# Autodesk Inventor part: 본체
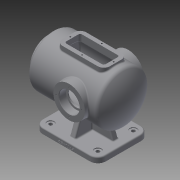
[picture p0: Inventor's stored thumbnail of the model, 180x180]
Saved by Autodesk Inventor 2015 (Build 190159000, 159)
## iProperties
Created: 2021-11
Part Number: 본체
Material: 일반
Document SubType Name: Modeling
Designer: 101698
Mass: 1311.33 g
Surface Area: 2404.16 cm^2
Volume: 1311.33 cm^3
Density: 1 g/cm^3
Appearance: 기본값
Author: 101698
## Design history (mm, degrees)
sketch "스케치1"
  geometry: L1 (-80, -65)-(80, -65); L2 (80, -65)-(80, 65); L3 (80, 65)-(-80, 65); L4 (-80, 65)-(-80, -65); L5 (-80, -65)-(80, 65); L6 (80, -65)-(-80, 65); 1 further point
  constraints: 12 end point, 2 midpoint, 2 parallel, 1 horizontal, 1 perpendicular
  dimensions: "d0" = 160 distance of L1.start L1.end; "d1" = 130 distance of L1.end L2.end
extrude "돌출1" new body sketch "스케치1" distance "d2" = 14; taper "d3" = 0 deg
sketch "스케치2"
  geometry: L1 (-7, -50)-(7, -50); L2 (7, -50)-(7, 50); L3 (7, 50)-(-7, 50); L4 (-7, 50)-(-7, -50); L5 (-7, -50)-(7, 50); L6 (7, -50)-(-7, 50); 1 further point
  constraints: 12 end point, 2 midpoint, 2 parallel, 1 horizontal, 1 perpendicular
  dimensions: "d4" = 14 distance of L2.end L3.end; "d5" = 100 distance of L1.end L2.end
extrude "돌출2" join sketch "스케치2" distance "d6" = 100; taper "d7" = 0 deg
sketch "스케치3"
  geometry: L1 (-7, -50)-(-7, 50) reference; L2 (-7, 50)-(7, 50) reference; L3 (7, 50)-(7, -50) reference; L4 (7, -50)-(-7, -50) reference; L5 (-80, -65)-(-80, 65) reference; L6 (-80, 65)-(80, 65) reference; L7 (80, 65)-(80, -65) reference; L8 (80, -65)-(-80, -65) reference; L9 (-60, -7)-(60, -7); L10 (60, -7)-(60, 7); L11 (60, 7)-(-60, 7); L12 (-60, 7)-(-60, -7); L13 (-60, -7)-(60, 7); L14 (60, -7)-(-60, 7); 1 further point
  constraints: 12 end point, 2 midpoint, 2 parallel, 1 horizontal, 1 perpendicular
  dimensions: "d8" = 14 distance of L11.end L9.start; "d9" = 120 distance of L10.end L11.end
extrude "돌출3" join sketch "스케치3" distance "d10" = 100; taper "d11" = 0 deg
feature "면 기울기1" dims angle "d12" = 20 deg
feature "면 기울기2" dims angle "d13" = 20 deg
feature "면 기울기3" dims angle "d14" = 20 deg
feature "면 기울기4" dims angle "d15" = 20 deg
sketch "스케치8"
  geometry: L1 (-80, 0)-(-80, 14) reference; L2 (-80, 14)-(-60, 14) reference; L3 (-60, 14)-(-23.603, 114) reference; L4 (-23.603, 114)-(23.603, 114) reference; L5 (23.603, 114)-(60, 14) reference; L6 (60, 14)-(80, 14) reference; L7 (80, 14)-(80, 0) reference; L8 (80, 0)-(-80, 0) reference; L9 (-75.993, 179)-(100, 179); L10 (106.737, 51.75)-(-106.612, 176.178); L11 (-109.588, 46.16)-(109.588, 181.84); L12 (-100, 114)-(100, 114); L13 (100, 179)-(100, 114); L14 (80, 0)-(-80, 0) reference; A1 r 95.786 centre (0, 114) between (80, 61.322) and (82.742, 65.743); A2 r 100 centre (0, 114) between (-75.993, 179) and (-100, 114); 3 further points
  constraints: 10 end point, 4 point on circle, 3 midpoint, 3 point on line, 2 centre point, 2 parallel, 1 coincident, 1 horizontal, 1 perpendicular
  dimensions: "d33" = 10 distance of L9.end L11.end; "d34" = 200 distance of L12.start L12.end; "d35" = 65 distance of L9.end L12.end; "d36" = 100 radius of A2; "d142" = 114 vertical distance of L7.end L12.end; "d143" = 20 distance from line of L7 L12.end
revolve "회전1" sketch "스케치8" stored, may be unused: angle "d37" = 90 deg
sketch "스케치10"
  geometry: C1 r 65 at (0, 0) reference; C2 r 47.5 at (0, 0); 1 further point
  constraints: 1 centre point, 1 coincident
  dimensions: "d41" = 95 diameter of C2
extrude "돌출7" join sketch "스케치10" distance "d42" = 10; taper "d43" = 0 deg
sketch "스케치11"
  geometry: C1 r 47.5 at (0, 0) reference; 1 further point
hole "구멍1" sketch "스케치11" at (0, 0) diameter "d44" = 65; stored, may be unused: countersink angle "d48" = 90 deg, drill point angle "d50" = 118 deg; dims "d45" = 6, "d46" = 4, "d47" = 2, "d49" = 40
sketch "스케치12"
  geometry: C1 r 32.5 at (0, 0) reference; 2 further points
  constraints: 1 horizontal alignment
  dimensions: "d51" = 40 distance of C1.centre point (40, 0)
hole "구멍2" sketch "스케치12" at (40, 0) diameter "d52" = 3.242; stored, may be unused: countersink angle "d56" = 90 deg, drill point angle "d58" = 118 deg; dims "d53" = 11, "d54" = 4, "d55" = 2, "d57" = 13
node "작업 평면1"
sketch "스케치13"
  geometry: C1 r 40 at (-17, 114); 1 further point
  constraints: 1 centre point
  dimensions: "d63" = 80 diameter of C1; "d64" = 17 horizontal distance of point (0, 0) C1.centre; "d65" = 114 vertical distance of point (0, 0) C1.centre
extrude "돌출8" join sketch "스케치13" distance "d66" = 150; taper "d67" = 0 deg
node "작업 평면2"
sketch "스케치15"
  geometry: L1 (-60, -30)-(60, -30); L2 (60, -30)-(60, 30); L3 (60, 30)-(-60, 30); L4 (-60, 30)-(-60, -30); L5 (-60, -30)-(60, 30); L6 (60, -30)-(-60, 30); 1 further point
  constraints: 12 end point, 2 midpoint, 2 parallel, 1 horizontal, 1 perpendicular
  dimensions: "d69" = 120 distance of L2.end L3.end; "d70" = 60 distance of L3.end L1.start
extrude "돌출9" join sketch "스케치15" stored distance "d71" = 150; taper "d72" = 0 deg
sketch "스케치16"
  geometry: L1 (-50, -20)-(50, -20); L2 (50, -20)-(50, 20); L3 (50, 20)-(-50, 20); L4 (-50, 20)-(-50, -20); L5 (-50, -20)-(50, 20); L6 (50, -20)-(-50, 20); 1 further point
  constraints: 12 end point, 2 midpoint, 2 parallel, 1 horizontal, 1 perpendicular
  dimensions: "d73" = 100 distance of L2.end L3.end; "d74" = 40 distance of L1.end L2.end
extrude "돌출10" cut sketch "스케치16" distance "d75" = 30; taper "d76" = 0 deg
sketch "스케치17"
  geometry: C1 r 40 at (0, 0) reference; 1 further point
hole "구멍3" sketch "스케치17" at (0, 0) diameter "d77" = 42; stored, may be unused: countersink angle "d81" = 90 deg, drill point angle "d83" = 118 deg; dims "d78" = 11, "d79" = 52, "d80" = 18, "d82" = 13
sketch "스케치18"
  geometry: C1 r 21 at (0, 0) reference; C2 r 40 at (0, 0) reference; C3 r 26 at (0, 0); 1 further point
  constraints: 1 centre point, 1 coincident
  dimensions: "d84" = 52 diameter of C3
extrude "돌출11" cut sketch "스케치18" distance "d85" = 18; taper "d86" = 0 deg
sketch "스케치19"
  geometry: C1 r 26 at (0, 0) reference; 2 further points
  constraints: 1 horizontal alignment
  dimensions: "d87" = 32.5 distance of point (32.5, 0) C1.centre
hole "구멍4" sketch "스케치19" at (32.5, 0) diameter "d88" = 3.242; stored, may be unused: countersink angle "d92" = 90 deg, drill point angle "d94" = 118 deg; dims "d89" = 11, "d90" = 52, "d91" = 18, "d93" = 13
sketch "스케치20"
  geometry: 5 further points
  constraints: 2 horizontal alignment, 1 vertical alignment
  dimensions: "d98" = 25 distance of point (0, 0) point (0, 25); "d99" = 25 distance of point (0, 0) point (0, -25); "d100" = 55 distance of point (0, 0) point (-55, 0); "d101" = 55 distance of point (55, 0) point (0, 0)
hole "구멍5" sketch "스케치20" at (0, 25), (0, -25), (55, 0), (-55, 0) diameter "d102" = 3.242; stored, may be unused: countersink angle "d106" = 90 deg, drill point angle "d108" = 118 deg; dims "d103" = 9, "d104" = 52, "d105" = 18, "d107" = 11
fillet "모깎기1" dims "d109" = 5
fillet "모깎기2" dims "d110" = 15
sketch "스케치21"
  geometry: L1 (-47.261, 49)-(-75.993, 49) reference; L2 (-75.993, 179)-(-60, 179) reference; L3 (-60, 179)-(-60, 184) reference; L4 (-60, 184)-(-56.621, 184) reference; L5 (-56.621, 184)-(-56.621, 173) reference; L6 (-56.621, 173)-(-55, 172.026) reference; L7 (-55, 172.026)-(-53.379, 173) reference; L8 (-53.379, 173)-(-53.379, 184) reference; L9 (-53.379, 184)-(-50, 184) reference; L10 (-50, 184)-(-50, 154) reference; L11 (-50, 154)-(50, 154) reference; L12 (50, 154)-(50, 184) reference; L13 (50, 184)-(53.379, 184) reference; L14 (53.379, 184)-(53.379, 173) reference; L15 (53.379, 173)-(55, 172.026) reference; L16 (55, 172.026)-(56.621, 173) reference; L17 (56.621, 173)-(56.621, 184) reference; L18 (56.621, 184)-(60, 184) reference; L19 (60, 184)-(60, 179) reference; L20 (60, 179)-(100, 179) reference; L21 (100, 179)-(100, 161.5) reference; L22 (100, 161.5)-(110, 161.5) reference; L23 (110, 161.5)-(110, 155.621) reference; L24 (110, 155.621)-(97, 155.621) reference; L25 (97, 155.621)-(96.026, 154) reference; L26 (96.026, 154)-(97, 152.379) reference; L27 (97, 152.379)-(110, 152.379) reference; L28 (110, 152.379)-(110, 146.5) reference; L29 (110, 146.5)-(70, 146.5) reference; L30 (70, 146.5)-(50.472, 114) reference; L31 (50.472, 114)-(70, 81.5) reference; L32 (70, 81.5)-(110, 81.5) reference; L33 (110, 81.5)-(110, 75.621) reference; L34 (110, 75.621)-(97, 75.621) reference; L35 (97, 75.621)-(96.026, 74) reference; L36 (96.026, 74)-(97, 72.379) reference; L37 (97, 72.379)-(110, 72.379) reference; L38 (110, 72.379)-(110, 66.5) reference; L39 (110, 66.5)-(100, 66.5) reference; L40 (100, 66.5)-(100, 49) reference; L41 (100, 49)-(47.261, 49) reference; L42 (47.261, 49)-(60, 14) reference; L43 (60, 14)-(80, 14) reference; L44 (80, 14)-(80, 0) reference; L45 (80, 0)-(-80, 0) reference; L46 (-80, 0)-(-80, 14) reference; L47 (-80, 14)-(-60, 14) reference; L48 (-60, 14)-(-47.261, 49) reference; L49 (85, 114)-(-90, 114); L50 (85, 114)-(85, 169); L51 (85, 169)-(-69.75, 169); C1 r 21 at (-17, 114) reference; A1 r 100 centre (0, 114) between (-75.993, 179) and (-75.993, 49) reference; A2 r 90 centre (0, 114) between (-72.155, 167.793) and (-90, 114); A3 r 3 centre (-69.75, 166) between (-69.75, 169) and (-72.155, 167.793); 2 further points
  constraints: 6 end point, 5 point on circle, 2 centre point, 2 tangent, 1 horizontal, 1 perpendicular, 1 point on line, 1 vertical
  dimensions: "d111" = 10 radial gap between concentric circles of A1 A2; "d112" = 10 distance between parallel lines of L51 L2; "d113" = 15 distance between parallel lines of L21 L50; "d114" = 114 distance between parallel lines of L45 L49; "d116" = 3 radius of A3
revolve "회전2" sketch "스케치21" stored, may be unused: angle "d115" = 90 deg
fillet "모깎기3" dims "d117" = 10
fillet "모깎기4" dims "d118" = 3
fillet "모깎기5" dims "d119" = 10
fillet "모깎기6" dims "d120" = 3
fillet "모깎기7" dims "d121" = 3
fillet "모깎기8" dims "d122" = 3
fillet "모깎기9" dims "d123" = 3
fillet "모깎기10" dims "d124" = 20
sketch "스케치22"
  geometry: A1 r 17 centre (-60, 45) between (-60, 62) and (-77, 45) reference; A2 r 17 centre (-60, -45) between (-77, -45) and (-60, -62) reference; A3 r 17 centre (60, -45) between (60, -62) and (77, -45) reference; 1 further point
hole "구멍6" sketch "스케치22" at (-60, -45), (60, -45), (-60, 45) diameter "d125" = 9; stored, may be unused: countersink angle "d129" = 90 deg, drill point angle "d131" = 118 deg; dims "d126" = 9, "d127" = 18, "d128" = 2, "d130" = 11
sketch "스케치23"
  geometry: A1 r 17 centre (60, 45) between (77, 45) and (60, 62) reference; 1 further point
hole "구멍7" sketch "스케치23" at (60, 45) diameter "d132" = 9; stored, may be unused: countersink angle "d136" = 90 deg, drill point angle "d138" = 118 deg; dims "d133" = 9, "d134" = 18, "d135" = 2, "d137" = 11
sketch "스케치24"
  geometry: L1 (0, 0)-(120, 0) reference; 4 further points
  constraints: 2 midpoint, 2 vertical alignment, 1 other
  dimensions: "d139" = 5 distance of point (60, 0) point (60, 5)
feature "엠보싱1" sketch "스케치24" dims "d140" = 0.5, "d141" = 0
fillet "모깎기11" dims "d144" = 0.3
chamfer "모따기1" distance "d145" = 1; stored, may be unused: second distance "d146" = 2, angle "d147" = 45 deg
node "솔리드1"
pattern_circular "원형 패턴1" dims angle "d60" = 360 deg
pattern_circular "원형 패턴2" dims angle "d96" = 360 deg
mirror "대칭1"
node "절단 모서리 투영1"
node "절단 모서리 투영4"
node "절단 모서리 투영5"
other parameters: "d62" = -75, "d68" = 184
